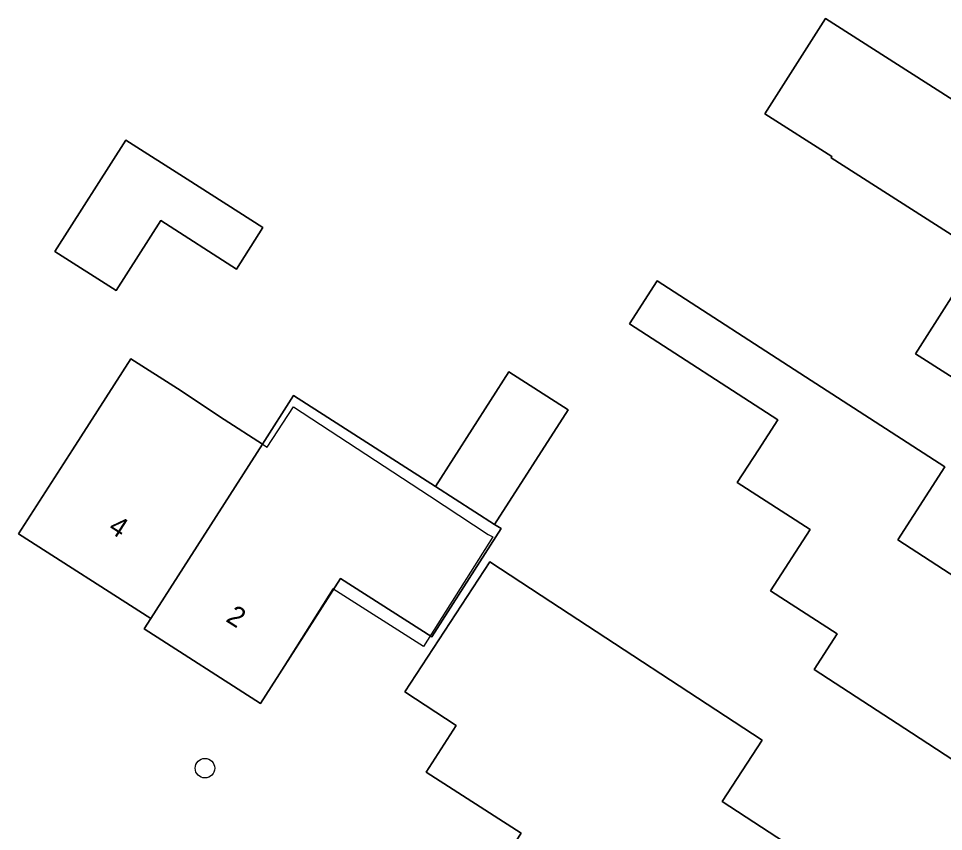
# Model space of a CAD drawing. Extents: x 161139 to 161601, y 381708 to 382245.
# Drawn here: x 161395.72 to 161442.02, y 381929.18 to 381969.87 of the extents above; entities that cross this region are included whole.
import ezdxf

# ---------------------------------------------------------------- set-up
doc = ezdxf.new("R2010")
doc.units = 0
for name, color, linetype in [('IMGEO_Boom', 7, 'Continuous'), ('IMGEO_Erf', 7, 'Continuous'), ('IMGEO_Pand', 7, 'Continuous'), ('IMGEO_Pand_nummerreeks', 7, 'Continuous'), ('IMGEO_Pand_vergunning_verleend', 7, 'Continuous')]:
    doc.layers.add(name, color=color, linetype=linetype)

msp = doc.modelspace()

# ---------------------------------------------------------------- linework, layer by layer
at = {"layer": 'IMGEO_Boom'}
msp.add_circle((161405.049, 381932.349), 0.489, dxfattribs=at)
at = {"layer": 'IMGEO_Erf'}
for points in [[(161436.113, 381969.868), (161453.299, 381958.899), (161451.149, 381955.529), (161454.905, 381953.132), (161454.472, 381952.454), (161457.1, 381950.777), (161455.205, 381947.808), (161455.632, 381947.535), (161453.984, 381944.959), (161453.554, 381945.234), (161453.216, 381944.706), (161445.564, 381949.575), (161445.725, 381949.828), (161440.611, 381953.092), (161443.837, 381958.147), (161436.391, 381962.9), (161436.43, 381962.961), (161433.072, 381965.105)], [(161401.095, 381963.786), (161404.162, 381961.827), (161407.953, 381959.405), (161406.629, 381957.331), (161402.837, 381959.753), (161400.602, 381956.254), (161397.535, 381958.213)], [(161426.297, 381954.589), (161427.683, 381956.735), (161435.118, 381951.933), (161442.093, 381947.428), (161439.732, 381943.773), (161444.594, 381940.628), (161448.782, 381937.896), (161446.736, 381934.759), (161447.131, 381934.501), (161445.19, 381931.527), (161444.844, 381931.753), (161444.6, 381931.379), (161440.412, 381934.111), (161435.544, 381937.289), (161436.694, 381939.07), (161433.36, 381941.223), (161435.339, 381944.288), (161431.697, 381946.644), (161432.758, 381948.284), (161433.731, 381949.788)], [(161401.34, 381952.83), (161403.671, 381951.359), (161406.003, 381949.799), (161407.925, 381948.568), (161409.478, 381950.994), (161416.59, 381946.44), (161420.268, 381952.184), (161423.224, 381950.291), (161419.546, 381944.547), (161419.872, 381944.339), (161416.401, 381938.917), (161411.831, 381941.842), (161410.527, 381939.805), (161407.83, 381935.594), (161402.006, 381939.323), (161402.334, 381939.835), (161395.716, 381944.073), (161398.412, 381948.284)], [(161419.303, 381942.671), (161421.878, 381940.989), (161432.947, 381933.757), (161430.94, 381930.685), (161438.43, 381925.79), (161433.961, 381918.951), (161429.542, 381921.839), (161428.584, 381920.374), (161422.791, 381924.16), (161419.192, 381926.512), (161420.883, 381929.103), (161416.127, 381932.149), (161417.632, 381934.492), (161415.057, 381936.174)]]:
    msp.add_lwpolyline(points, close=True, dxfattribs=at)
at = {"layer": 'IMGEO_Pand'}
for points in [[(161453.299, 381958.899), (161436.113, 381969.868), (161433.072, 381965.105), (161436.43, 381962.961), (161436.391, 381962.9), (161443.837, 381958.147), (161440.611, 381953.092), (161445.725, 381949.828), (161445.564, 381949.575), (161453.216, 381944.706), (161453.554, 381945.234), (161453.984, 381944.959), (161455.632, 381947.535), (161455.205, 381947.808), (161457.1, 381950.777), (161454.472, 381952.454), (161454.905, 381953.132), (161451.149, 381955.529)], [(161404.162, 381961.827), (161401.095, 381963.786), (161397.535, 381958.213), (161400.602, 381956.254), (161402.837, 381959.753), (161406.629, 381957.331), (161407.953, 381959.405)], [(161439.732, 381943.773), (161442.093, 381947.428), (161435.118, 381951.933), (161427.683, 381956.735), (161426.297, 381954.589), (161433.731, 381949.788), (161432.758, 381948.284), (161431.697, 381946.644), (161435.339, 381944.288), (161433.36, 381941.223), (161436.694, 381939.07), (161435.544, 381937.289), (161440.412, 381934.111), (161444.6, 381931.379), (161444.844, 381931.753), (161445.19, 381931.527), (161447.131, 381934.501), (161446.736, 381934.759), (161448.782, 381937.896), (161444.594, 381940.628)], [(161407.925, 381948.568), (161406.003, 381949.799), (161403.671, 381951.359), (161401.34, 381952.83), (161398.412, 381948.284), (161395.716, 381944.073), (161402.334, 381939.835)], [(161420.268, 381952.184), (161416.59, 381946.44), (161419.546, 381944.547), (161423.224, 381950.291)], [(161419.872, 381944.339), (161419.546, 381944.547), (161416.59, 381946.44), (161409.478, 381950.994), (161407.925, 381948.568), (161402.334, 381939.835), (161402.006, 381939.323), (161407.83, 381935.594), (161410.527, 381939.805), (161411.831, 381941.842), (161416.401, 381938.917)], [(161430.94, 381930.685), (161432.947, 381933.757), (161421.878, 381940.989), (161419.303, 381942.671), (161415.057, 381936.174), (161417.632, 381934.492), (161416.127, 381932.149), (161420.883, 381929.103), (161419.192, 381926.512), (161422.791, 381924.16), (161428.584, 381920.374), (161429.542, 381921.839), (161433.961, 381918.951), (161438.43, 381925.79)]]:
    msp.add_lwpolyline(points, close=True, dxfattribs=at)
at = {"layer": 'IMGEO_Pand_vergunning_verleend'}
msp.add_lwpolyline([(161402.006, 381939.323), (161402.334, 381939.835), (161407.925, 381948.568), (161408.156, 381948.417), (161409.477, 381950.435), (161416.288, 381945.978), (161419.231, 381944.052), (161419.455, 381943.928), (161415.992, 381938.447), (161411.447, 381941.319), (161407.83, 381935.594)], close=True, dxfattribs=at)

# ---------------------------------------------------------------- texts
at = {"layer": 'IMGEO_Pand_nummerreeks'}
for s, rotation, p in [('4', 327.3643, (161400.152, 381944.225)), ('2', 327.3701, (161406.044, 381939.731))]:
    msp.add_text(s, height=1, rotation=rotation, dxfattribs=at).set_placement(p)

doc.saveas('drawing.dxf')
